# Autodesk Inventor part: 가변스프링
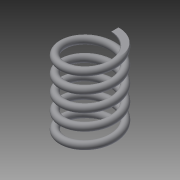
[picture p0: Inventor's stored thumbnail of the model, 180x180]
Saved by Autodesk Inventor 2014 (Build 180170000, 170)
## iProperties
Created: 2019-10
Part Number: 가변스프링
Material: Generic
Document SubType Name: Modeling
Designer: kh
Density: 1 g/cm^3
Appearance: Default
Mass: 18.3033 g
Surface Area: 124.212 cm^2
Volume: 18.3033 cm^3
Author: kh
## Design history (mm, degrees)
sketch "Sketch1"
  geometry: L1 (0, 0)-(21, 0); L2 (21, 0)-(21, 67.25); L3 (21, 67.25)-(0, 67.25); L4 (0, 67.25)-(0, 0); C1 r 3 at (21, 0)
  constraints: 8 end point, 2 parallel, 1 centre point, 1 coincident, 1 horizontal, 1 perpendicular
  dimensions: "d0" = 6 diameter of C1; "d1" = 42 diameter of L2 L4; "d2" = 67.25 distance of L1.end L2.end (derived)
coil "Coil1" sketch "Sketch1" pitch "d3" = 10; turns "d5" = 5; dims "d4" = 67.25 (= d2), "d6" = 0, angle "d7" = 90 deg, angle "d8" = 90 deg, "d9" = 0, "d10" = 0
split "Split1"
workplane "Work Plane1"
split "Split2"
body "Solid1"
other parameters: "d11" = 67.25 (= d2)
